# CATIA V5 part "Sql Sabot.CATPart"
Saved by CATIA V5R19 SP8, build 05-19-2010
Part number: Sql Sabot
Publications: "Plan.1", "Droite.1", "Point.3"
Bounding box of the stored display mesh (mm): x 0 to 0, y 0 to 0, z -1620 to -1300
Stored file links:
  G:\EU_thinkMotion\CFAO_2010\MMS_groupe3\MMS_groupe3\rdalborgo\rdalborgo\Sql Sabot.CATPart
  G:\EU_thinkMotion\CFAO_2010\MMS_groupe3\MMS_groupe3\rdalborgo\rdalborgo\rdalborgo.CATProduct
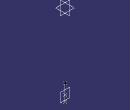
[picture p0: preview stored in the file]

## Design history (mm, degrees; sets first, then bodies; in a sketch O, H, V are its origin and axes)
Set1
  Plane1: linked copy from another document
  Point1 "B verin frein": linked copy from another document
  Plane2: linked copy from another document
  Point2 "Axe sabot": linked copy from another document
Set2
  Plane3: type OffsetPt, RefPlane Plane2, RefPoint Point1
  Line1: type PtPt, FirstPoint Point2, SecondPoint Point3
  Point3: (0, 0, -120), relative to Point1
Body1 (main body)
